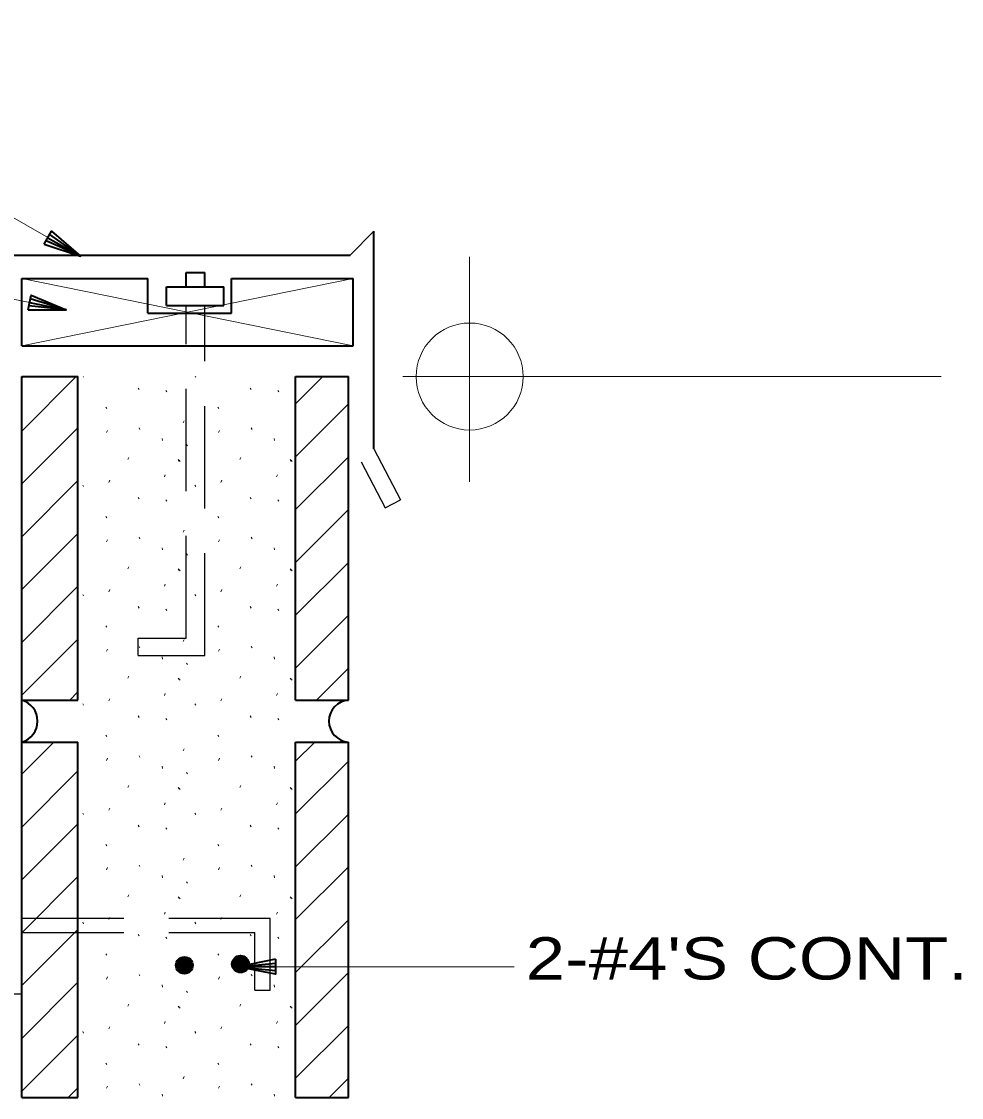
# Model space of a CAD drawing. Extents: x 11001.56 to 11007.08, y 10014.75 to 10021.39.
# Drawn here: x 11004.983 to 11007.08, y 10018.943 to 10021.343 of the extents above; entities that cross this region are included whole.
import ezdxf

# ---------------------------------------------------------------- set-up
doc = ezdxf.new("R2010")
doc.units = 0
doc.header["$LTSCALE"] = 0.038
doc.linetypes.add('LONG_DASHED', pattern=[7.5, 6, -1.5])
for name, color, linetype, lineweight in [('1', 7, 'Continuous', 13), ('46', 7, 'Continuous', 35), ('54', 7, 'Continuous', 35)]:
    doc.layers.add(name, color=color, linetype=linetype, lineweight=lineweight)

msp = doc.modelspace()

# ---------------------------------------------------------------- linework, layer by layer
at = {"layer": '1', "lineweight": 25}
for p, q in [((11005.71619, 10020.82199), (11005.76951, 10020.87531)), ((11005.76951, 10020.38981), (11005.82868, 10020.27618)), ((11004.9839, 10019.17344), (11004.95453, 10019.17344))]:
    msp.add_line(p, q, dxfattribs=at)
at = {"layer": '1', "lineweight": 35}
for p, q in [((11005.76951, 10020.38981), (11005.76951, 10020.87531)), ((11004.86176, 10020.82199), (11005.71619, 10020.82199)), ((11005.35071, 10020.78341), (11005.39252, 10020.78341)), ((11005.35071, 10020.75354), (11005.35071, 10020.78341)), ((11005.39252, 10020.75155), (11005.39252, 10020.78341)), ((11004.9839, 10020.61979), (11004.9839, 10020.76983)), ((11004.9839, 10020.76983), (11005.26491, 10020.76983)), ((11005.26491, 10020.69227), (11005.26491, 10020.76983)), ((11005.45182, 10020.69227), (11005.45182, 10020.76983)), ((11005.45182, 10020.76983), (11005.72329, 10020.76983)), ((11005.72329, 10020.61979), (11005.72329, 10020.76983)), ((11005.30692, 10020.75155), (11005.43432, 10020.75155)), ((11005.30692, 10020.70974), (11005.30692, 10020.75155)), ((11005.43432, 10020.70974), (11005.43432, 10020.75155)), ((11005.30692, 10020.70974), (11005.43432, 10020.70974)), ((11005.26491, 10020.69227), (11005.45182, 10020.69227)), ((11004.9839, 10020.61979), (11005.72329, 10020.61979)), ((11004.9839, 10020.61979), (11005.13994, 10020.61979)), ((11004.9839, 10020.55128), (11005.1091, 10020.55128)), ((11004.9839, 10019.73521), (11004.9839, 10020.55128)), ((11005.1091, 10019.82965), (11005.1091, 10020.55128)), ((11005.59473, 10020.55128), (11005.71231, 10020.55128)), ((11005.59473, 10019.82965), (11005.59473, 10020.55128)), ((11005.71231, 10019.82965), (11005.71231, 10020.55128)), ((11004.9839, 10019.82965), (11005.1091, 10019.82965)), ((11005.59473, 10019.82965), (11005.71231, 10019.82965)), ((11004.9839, 10019.7359), (11005.1091, 10019.7359)), ((11004.9839, 10018.94324), (11004.9839, 10019.7359)), ((11005.1091, 10018.94324), (11005.1091, 10019.7359)), ((11005.59473, 10019.7359), (11005.71231, 10019.7359)), ((11005.59473, 10018.94324), (11005.59473, 10019.7359)), ((11005.71231, 10018.94324), (11005.71231, 10019.7359)), ((11004.9839, 10018.94324), (11005.1091, 10018.94324)), ((11005.59473, 10018.94324), (11005.71231, 10018.94324))]:
    msp.add_line(p, q, dxfattribs=at)
at = {"layer": '1'}
for p, q in [((11004.9839, 10020.76983), (11005.72329, 10020.61979)), ((11005.72329, 10020.76983), (11004.9839, 10020.61979)), ((11004.9839, 10020.42972), (11005.10545, 10020.55128)), ((11004.9839, 10020.54757), (11004.98759, 10020.55128)), ((11005.12097, 10020.55128), (11005.12196, 10020.54979)), ((11005.37096, 10020.55128), (11005.37196, 10020.54979)), ((11005.59473, 10020.49039), (11005.65562, 10020.55128)), ((11005.24353, 10020.52562), (11005.24561, 10020.52249)), ((11005.30521, 10020.51998), (11005.30729, 10020.51684)), ((11005.49353, 10020.52562), (11005.49561, 10020.52249)), ((11005.55521, 10020.51998), (11005.55729, 10020.51684)), ((11005.59473, 10020.37253), (11005.7123, 10020.49011)), ((11005.17135, 10020.48291), (11005.17345, 10020.47977)), ((11005.42135, 10020.48291), (11005.42345, 10020.47977)), ((11005.34374, 10020.44785), (11005.34583, 10020.45255)), ((11005.59374, 10020.44785), (11005.59473, 10020.45007)), ((11004.9839, 10020.31187), (11005.1091, 10020.43708)), ((11005.17307, 10020.42646), (11005.17516, 10020.43116)), ((11005.24549, 10020.43657), (11005.24757, 10020.43344)), ((11005.42307, 10020.42646), (11005.42516, 10020.43116)), ((11005.49549, 10020.43657), (11005.49757, 10020.43344)), ((11005.29716, 10020.41335), (11005.29768, 10020.40866)), ((11005.35134, 10020.39951), (11005.35343, 10020.39637)), ((11005.54716, 10020.41335), (11005.54768, 10020.40866)), ((11005.22056, 10020.36592), (11005.22266, 10020.37061)), ((11005.47056, 10020.36592), (11005.47266, 10020.37061)), ((11005.59473, 10020.25469), (11005.7123, 10020.37226)), ((11005.33278, 10020.36591), (11005.33486, 10020.36278)), ((11005.33486, 10020.36472), (11005.33695, 10020.36158)), ((11005.58278, 10020.36591), (11005.58486, 10020.36278)), ((11005.58486, 10020.36472), (11005.58695, 10020.36158)), ((11005.30198, 10020.32722), (11005.30407, 10020.33192)), ((11005.55198, 10020.32722), (11005.55407, 10020.33192)), ((11004.9839, 10020.19403), (11005.1091, 10020.31923)), ((11005.11987, 10020.30912), (11005.12196, 10020.30599)), ((11005.17829, 10020.31522), (11005.18037, 10020.31992)), ((11005.36987, 10020.30912), (11005.37196, 10020.30599)), ((11005.42829, 10020.31522), (11005.43037, 10020.31992)), ((11005.24353, 10020.28182), (11005.24561, 10020.27869)), ((11005.30521, 10020.27618), (11005.30729, 10020.27304)), ((11005.49353, 10020.28182), (11005.49561, 10020.27869)), ((11005.55521, 10020.27618), (11005.55729, 10020.27304)), ((11005.59474, 10020.13684), (11005.7123, 10020.25441)), ((11005.17135, 10020.2391), (11005.17345, 10020.23597)), ((11005.42135, 10020.2391), (11005.42345, 10020.23597)), ((11004.9839, 10020.07618), (11005.1091, 10020.20137)), ((11005.34374, 10020.20405), (11005.34583, 10020.20875)), ((11005.59374, 10020.20405), (11005.59473, 10020.20627)), ((11005.17307, 10020.18266), (11005.17516, 10020.18735)), ((11005.24549, 10020.19277), (11005.24757, 10020.18964)), ((11005.42307, 10020.18266), (11005.42516, 10020.18735)), ((11005.49549, 10020.19277), (11005.49757, 10020.18964)), ((11005.29716, 10020.16955), (11005.29768, 10020.16485)), ((11005.35134, 10020.15571), (11005.35343, 10020.15257)), ((11005.54716, 10020.16955), (11005.54768, 10020.16485)), ((11005.59474, 10020.01899), (11005.7123, 10020.13656)), ((11005.22056, 10020.12211), (11005.22266, 10020.12681)), ((11005.33278, 10020.1221), (11005.33486, 10020.11898)), ((11005.33486, 10020.12092), (11005.33695, 10020.11778)), ((11005.47056, 10020.12211), (11005.47266, 10020.12681)), ((11005.58278, 10020.1221), (11005.58486, 10020.11898)), ((11005.58486, 10020.12092), (11005.58695, 10020.11778)), ((11004.9839, 10019.95832), (11005.1091, 10020.08353)), ((11005.30198, 10020.08342), (11005.30407, 10020.08811)), ((11005.55198, 10020.08342), (11005.55407, 10020.08811)), ((11005.11987, 10020.06532), (11005.12196, 10020.06219)), ((11005.17829, 10020.07142), (11005.18037, 10020.07611)), ((11005.36987, 10020.06532), (11005.37196, 10020.06219)), ((11005.42829, 10020.07142), (11005.43037, 10020.07611)), ((11005.24353, 10020.03802), (11005.24561, 10020.03489)), ((11005.30521, 10020.03237), (11005.30729, 10020.02924)), ((11005.49353, 10020.03802), (11005.49561, 10020.03489)), ((11005.55521, 10020.03237), (11005.55729, 10020.02924)), ((11005.59474, 10019.90114), (11005.71231, 10020.01872)), ((11005.17135, 10019.9953), (11005.17345, 10019.99217)), ((11005.42135, 10019.9953), (11005.42345, 10019.99217)), ((11004.9839, 10019.84047), (11005.1091, 10019.96568)), ((11005.34374, 10019.96025), (11005.34583, 10019.96495)), ((11005.59374, 10019.96025), (11005.59473, 10019.96247)), ((11005.17307, 10019.93885), (11005.17516, 10019.94355)), ((11005.24549, 10019.94897), (11005.24757, 10019.94583)), ((11005.42307, 10019.93885), (11005.42516, 10019.94355)), ((11005.49549, 10019.94897), (11005.49757, 10019.94583)), ((11005.29716, 10019.92575), (11005.29768, 10019.92105)), ((11005.54716, 10019.92575), (11005.54768, 10019.92105)), ((11005.35134, 10019.91191), (11005.35343, 10019.90877)), ((11005.64109, 10019.82965), (11005.71231, 10019.90086)), ((11005.22056, 10019.87831), (11005.22266, 10019.88301)), ((11005.33278, 10019.8783), (11005.33486, 10019.87518)), ((11005.33486, 10019.87711), (11005.33695, 10019.87398)), ((11005.47056, 10019.87831), (11005.47266, 10019.88301)), ((11005.58278, 10019.8783), (11005.58486, 10019.87518)), ((11005.58486, 10019.87711), (11005.58695, 10019.87398)), ((11005.09093, 10019.82965), (11005.1091, 10019.84782)), ((11005.30198, 10019.83961), (11005.30407, 10019.84431)), ((11005.55198, 10019.83961), (11005.55407, 10019.84431)), ((11005.11987, 10019.82152), (11005.12196, 10019.81839)), ((11005.17829, 10019.82761), (11005.18037, 10019.83231)), ((11005.36987, 10019.82152), (11005.37196, 10019.81839)), ((11005.42829, 10019.82761), (11005.43037, 10019.83231)), ((11005.24353, 10019.79422), (11005.24561, 10019.79108)), ((11005.49353, 10019.79422), (11005.49561, 10019.79108)), ((11005.30521, 10019.78857), (11005.30729, 10019.78544)), ((11005.55521, 10019.78857), (11005.55729, 10019.78544)), ((11005.17135, 10019.7515), (11005.17345, 10019.74836)), ((11005.42135, 10019.7515), (11005.42345, 10019.74836)), ((11004.9839, 10019.6643), (11005.05549, 10019.7359)), ((11005.34374, 10019.71645), (11005.34583, 10019.72115)), ((11005.59473, 10019.69341), (11005.63721, 10019.7359)), ((11005.17307, 10019.69505), (11005.17516, 10019.69975)), ((11005.24549, 10019.70517), (11005.24757, 10019.70203)), ((11005.42307, 10019.69505), (11005.42516, 10019.69975)), ((11005.49549, 10019.70517), (11005.49757, 10019.70203)), ((11005.59374, 10019.71645), (11005.59473, 10019.71867)), ((11005.29716, 10019.68195), (11005.29768, 10019.67725)), ((11005.54716, 10019.68195), (11005.54768, 10019.67725)), ((11005.59473, 10019.57555), (11005.71231, 10019.69315)), ((11004.9839, 10019.54645), (11005.1091, 10019.67166)), ((11005.35134, 10019.6681), (11005.35343, 10019.66497)), ((11005.22056, 10019.63451), (11005.22266, 10019.63921)), ((11005.33278, 10019.6345), (11005.33486, 10019.63137)), ((11005.33486, 10019.63331), (11005.33695, 10019.63018)), ((11005.47056, 10019.63451), (11005.47266, 10019.63921)), ((11005.58278, 10019.6345), (11005.58486, 10019.63137)), ((11005.58486, 10019.63331), (11005.58695, 10019.63018)), ((11005.30198, 10019.59581), (11005.30407, 10019.60051)), ((11005.55198, 10019.59581), (11005.55407, 10019.60051)), ((11005.11987, 10019.57772), (11005.12196, 10019.57458)), ((11005.17829, 10019.58381), (11005.18037, 10019.58851)), ((11005.36987, 10019.57772), (11005.37196, 10019.57458)), ((11005.42829, 10019.58381), (11005.43037, 10019.58851)), ((11004.9839, 10019.42859), (11005.1091, 10019.5538)), ((11005.59473, 10019.45771), (11005.71231, 10019.57529)), ((11005.24353, 10019.55042), (11005.24561, 10019.54728)), ((11005.30521, 10019.54477), (11005.30729, 10019.54164)), ((11005.49353, 10019.55042), (11005.49561, 10019.54728)), ((11005.55521, 10019.54477), (11005.55729, 10019.54164)), ((11005.17135, 10019.5077), (11005.17345, 10019.50456)), ((11005.42135, 10019.5077), (11005.42345, 10019.50456)), ((11005.24549, 10019.46136), (11005.24757, 10019.45823)), ((11005.34374, 10019.47265), (11005.34583, 10019.47734)), ((11005.49549, 10019.46136), (11005.49757, 10019.45823)), ((11005.59374, 10019.47265), (11005.59473, 10019.47486)), ((11005.59474, 10019.33986), (11005.71231, 10019.45744)), ((11004.9839, 10019.31075), (11005.1091, 10019.43595)), ((11005.17307, 10019.45125), (11005.17516, 10019.45595)), ((11005.29716, 10019.43815), (11005.29768, 10019.43345)), ((11005.42307, 10019.45125), (11005.42516, 10019.45595)), ((11005.54716, 10019.43815), (11005.54768, 10019.43345)), ((11005.35134, 10019.4243), (11005.35343, 10019.42117)), ((11005.22056, 10019.39071), (11005.22266, 10019.39541)), ((11005.33278, 10019.3907), (11005.33486, 10019.38757)), ((11005.33486, 10019.38951), (11005.33695, 10019.38637)), ((11005.47056, 10019.39071), (11005.47266, 10019.39541)), ((11005.58278, 10019.3907), (11005.58486, 10019.38757)), ((11005.58486, 10019.38951), (11005.58695, 10019.38637)), ((11005.17829, 10019.34001), (11005.18037, 10019.34471)), ((11005.30198, 10019.35201), (11005.30407, 10019.35671)), ((11005.42829, 10019.34001), (11005.43037, 10019.34471)), ((11005.55198, 10019.35201), (11005.55407, 10019.35671)), ((11005.59474, 10019.22201), (11005.71231, 10019.33958)), ((11004.9839, 10019.1929), (11005.1091, 10019.3181)), ((11005.11987, 10019.33392), (11005.12196, 10019.33078)), ((11005.36987, 10019.33392), (11005.37196, 10019.33078)), ((11005.24353, 10019.30661), (11005.24561, 10019.30348)), ((11005.30521, 10019.30097), (11005.30729, 10019.29783)), ((11005.49353, 10019.30661), (11005.49561, 10019.30348)), ((11005.55521, 10019.30097), (11005.55729, 10019.29783)), ((11005.17135, 10019.2639), (11005.17345, 10019.26076)), ((11005.42135, 10019.2639), (11005.42345, 10019.26076)), ((11005.24549, 10019.21756), (11005.24757, 10019.21443)), ((11005.34374, 10019.22884), (11005.34583, 10019.23354)), ((11005.49549, 10019.21756), (11005.49757, 10019.21443)), ((11005.59374, 10019.22884), (11005.59473, 10019.23106)), ((11005.59474, 10019.10416), (11005.71232, 10019.22174)), ((11004.9839, 10019.07505), (11005.1091, 10019.20026)), ((11005.17307, 10019.20745), (11005.17516, 10019.21215)), ((11005.29716, 10019.19434), (11005.29768, 10019.18965)), ((11005.42307, 10019.20745), (11005.42516, 10019.21215)), ((11005.54716, 10019.19434), (11005.54768, 10019.18965)), ((11005.35134, 10019.1805), (11005.35343, 10019.17736)), ((11005.22056, 10019.14691), (11005.22266, 10019.1516)), ((11005.33278, 10019.1469), (11005.33486, 10019.14377)), ((11005.33486, 10019.14571), (11005.33695, 10019.14257)), ((11005.47056, 10019.14691), (11005.47266, 10019.1516)), ((11005.58278, 10019.1469), (11005.58486, 10019.14377)), ((11005.58486, 10019.14571), (11005.58695, 10019.14257)), ((11005.17829, 10019.09621), (11005.18037, 10019.10091)), ((11005.30198, 10019.10821), (11005.30407, 10019.11291)), ((11005.42829, 10019.09621), (11005.43037, 10019.10091)), ((11005.55198, 10019.10821), (11005.55407, 10019.11291)), ((11005.59473, 10018.9863), (11005.71231, 10019.10389)), ((11004.9839, 10018.9572), (11005.1091, 10019.08241)), ((11005.11987, 10019.09011), (11005.12196, 10019.08698)), ((11005.36987, 10019.09011), (11005.37196, 10019.08698)), ((11005.24353, 10019.06281), (11005.24561, 10019.05968)), ((11005.30521, 10019.05717), (11005.30729, 10019.05403)), ((11005.49353, 10019.06281), (11005.49561, 10019.05968)), ((11005.55521, 10019.05717), (11005.55729, 10019.05403)), ((11005.17135, 10019.02009), (11005.17345, 10019.01696)), ((11005.42135, 10019.02009), (11005.42345, 10019.01696)), ((11005.34374, 10018.98504), (11005.34583, 10018.98974)), ((11005.59374, 10018.98504), (11005.59473, 10018.98726)), ((11005.66952, 10018.94324), (11005.71231, 10018.98603)), ((11005.08779, 10018.94324), (11005.1091, 10018.96455)), ((11005.17307, 10018.96365), (11005.17516, 10018.96834)), ((11005.24549, 10018.97376), (11005.24757, 10018.97062)), ((11005.42307, 10018.96365), (11005.42516, 10018.96834)), ((11005.49549, 10018.97376), (11005.49757, 10018.97062)), ((11005.29716, 10018.95054), (11005.29768, 10018.94584)), ((11005.54716, 10018.95054), (11005.54768, 10018.94584))]:
    msp.add_line(p, q, dxfattribs=at)
at = {"layer": '1', "linetype": 'LONG_DASHED', "lineweight": 25}
for p, q in [((11005.35071, 10019.96773), (11005.35071, 10020.70974)), ((11005.39252, 10019.92927), (11005.39252, 10020.70974)), ((11005.24343, 10019.96773), (11005.35071, 10019.96773)), ((11005.24343, 10019.92927), (11005.24343, 10019.96773)), ((11005.24343, 10019.92927), (11005.39252, 10019.92927)), ((11004.9839, 10019.34295), (11005.53785, 10019.34295)), ((11005.53785, 10019.18249), (11005.53785, 10019.34295)), ((11004.9839, 10019.31123), (11005.50401, 10019.31123)), ((11005.50401, 10019.18249), (11005.50401, 10019.31123)), ((11005.50401, 10019.18249), (11005.53785, 10019.18249))]:
    msp.add_line(p, q, dxfattribs=at)
at = {"layer": '1', "lineweight": 25}
msp.add_lwpolyline([(11005.74105, 10020.3614), (11005.79466, 10020.25846), (11005.82868, 10020.27618)], dxfattribs=at)
at = {"layer": '1', "lineweight": 35}
for centre, radius, start, end in [((11004.97033, 10019.78277), 0.0488, 286.1421, 73.85791), ((11005.71595, 10019.78277), 0.04702, 94.43812, 265.56187)]:
    msp.add_arc(centre, radius, start, end, dxfattribs=at)
at = {"layer": '46', "lineweight": 13}
for p, q in [((11004.20014, 10021.34315), (11005.11464, 10020.81941)), ((11003.92667, 10020.93043), (11005.08307, 10020.70018)), ((11005.9829, 10020.31673), (11005.9829, 10020.81828)), ((11005.83356, 10020.55128), (11007.0347, 10020.55128)), ((11005.46658, 10019.23477), (11006.08222, 10019.23477))]:
    msp.add_line(p, q, dxfattribs=at)
at = {"layer": '46'}
for p, q in [((11005.11464, 10020.81941), (11005.03847, 10020.85409)), ((11005.04232, 10020.86082), (11005.11464, 10020.81941)), ((11005.08307, 10020.70018), (11004.99983, 10020.70884)), ((11005.00134, 10020.71645), (11005.08307, 10020.70018)), ((11005.46658, 10019.23477), (11005.54992, 10019.24252)), ((11005.54992, 10019.23477), (11005.46658, 10019.23477))]:
    msp.add_line(p, q, dxfattribs=at)
for points in [[(11005.03404, 10020.84635), (11005.0506, 10020.87528), (11005.11464, 10020.81941)], [(11005.03404, 10020.84635), (11005.11464, 10020.81941), (11005.04637, 10020.8679)], [(11004.99809, 10020.7001), (11005.00459, 10020.73279), (11005.08307, 10020.70018)], [(11004.99809, 10020.7001), (11005.08307, 10020.70018), (11005.00294, 10020.72445)], [(11005.54992, 10019.25144), (11005.54992, 10019.2181), (11005.46658, 10019.23477)], [(11005.54992, 10019.25144), (11005.46658, 10019.23477), (11005.54992, 10019.22661)]]:
    msp.add_lwpolyline(points, dxfattribs=at)
at = {"layer": '46', "lineweight": 13}
msp.add_circle((11005.9829, 10020.55128), 0.1193, dxfattribs=at)
at = {"layer": '54'}
for centre, radius in [((11005.34656, 10019.23802), 0.01891), ((11005.34656, 10019.23788), 0.01678), ((11005.34656, 10019.23788), 0.01481), ((11005.34663, 10019.23789), 0.01282), ((11005.34656, 10019.23789), 0.01062), ((11005.34656, 10019.23789), 0.00864), ((11005.34656, 10019.23789), 0.00638), ((11005.34656, 10019.23788), 0.00425), ((11005.47153, 10019.2408), 0.01891), ((11005.47153, 10019.24066), 0.01678), ((11005.47153, 10019.24066), 0.01481), ((11005.4716, 10019.24067), 0.01282), ((11005.47153, 10019.24067), 0.01062), ((11005.47153, 10019.24067), 0.00864), ((11005.47153, 10019.24067), 0.00638), ((11005.47153, 10019.24066), 0.00425), ((11005.47153, 10019.24066), 0.00226), ((11005.4716, 10019.24067), 0.00106), ((11005.34656, 10019.23788), 0.00226), ((11005.34663, 10019.23789), 0.00106)]:
    msp.add_circle(centre, radius, dxfattribs=at)

# ---------------------------------------------------------------- texts
at = {"layer": '46', "width": 1.25}
msp.add_text("2-#4'S CONT.", height=0.09445, dxfattribs=at).set_placement((11006.10779, 10019.20629))

doc.saveas('drawing.dxf')
